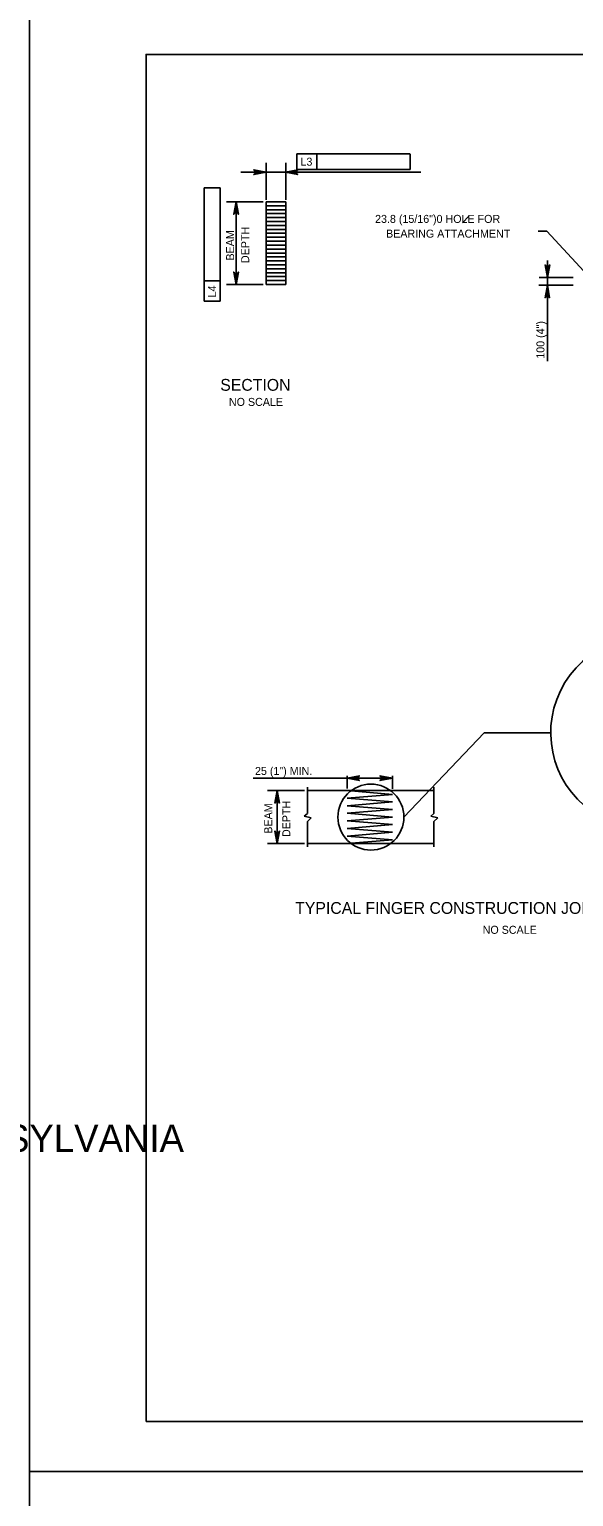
# Model space of a CAD drawing. Extents: x -13 to 81, y -176 to 0.
# Drawn here: x 34 to 42.16, y -66.38 to -44.38 of the extents above; entities that cross this region are included whole.
import ezdxf

# ---------------------------------------------------------------- set-up
doc = ezdxf.new("R2010")
doc.units = 0
for name, color, linetype in [('Level 1', 7, 'Continuous'), ('Level 2', 7, 'Continuous'), ('Level 5', 7, 'Continuous'), ('Level 6', 7, 'Continuous'), ('Level 63', 7, 'Continuous'), ('Level 7', 7, 'Continuous'), ('Level 8', 7, 'Continuous')]:
    doc.layers.add(name, color=color, linetype=linetype)

msp = doc.modelspace()

# ---------------------------------------------------------------- linework, layer by layer
at = {"layer": 'Level 1'}
msp.add_lwpolyline([(35.75, -65.25), (67.25, -65.25), (67.25, -44.75), (35.75, -44.75)], close=True, dxfattribs=at)
at = {"layer": 'Level 2'}
for p, q in [((37.553, -48.201), (37.553, -46.961)), ((37.553, -46.961), (37.848, -46.961)), ((37.848, -46.961), (37.848, -48.201)), ((37.848, -48.201), (37.553, -48.201))]:
    msp.add_line(p, q, dxfattribs=at)
at = {"layer": 'Level 5'}
for p, q in [((37.553, -46.931), (37.553, -46.378)), ((37.848, -46.931), (37.848, -46.378)), ((38.01, -46.241), (38.01, -46.477)), ((38.01, -46.241), (38.313, -46.241)), ((38.313, -46.241), (38.313, -46.477)), ((38.313, -46.241), (39.705, -46.241)), ((39.711, -46.241), (39.711, -46.477)), ((37.172, -46.518), (39.871, -46.518)), ((38.01, -46.477), (39.711, -46.477)), ((36.624, -46.75), (36.861, -46.75)), ((36.624, -48.148), (36.624, -46.75)), ((36.861, -48.451), (36.861, -46.75)), ((37.508, -46.961), (36.955, -46.961)), ((37.101, -48.201), (37.101, -46.961)), ((40.592, -47.178), (40.496, -47.274)), ((41.76, -47.399), (41.632, -47.399)), ((42.383, -48.07), (41.76, -47.399)), ((41.77, -49.352), (41.77, -47.842)), ((36.624, -48.451), (36.624, -48.148)), ((36.624, -48.148), (36.861, -48.148)), ((42.158, -48.095), (41.646, -48.095)), ((37.508, -48.201), (36.955, -48.201)), ((42.155, -48.213), (41.643, -48.213)), ((36.624, -48.451), (36.861, -48.451)), ((37.355, -55.603), (39.445, -55.603)), ((38.765, -55.758), (38.765, -55.565)), ((39.445, -55.764), (39.445, -55.568)), ((38.125, -55.789), (37.572, -55.789)), ((37.718, -56.583), (37.718, -55.789)), ((38.17, -56.131), (38.17, -55.739)), ((40.069, -55.739), (40.069, -56.133)), ((38.17, -56.131), (38.124, -56.17)), ((38.124, -56.17), (38.228, -56.197)), ((38.228, -56.197), (38.17, -56.251)), ((38.17, -56.634), (38.17, -56.251)), ((40.069, -56.133), (40.023, -56.172)), ((40.023, -56.172), (40.127, -56.199)), ((40.127, -56.199), (40.069, -56.253)), ((40.069, -56.253), (40.069, -56.634)), ((38.125, -56.583), (37.572, -56.583))]:
    msp.add_line(p, q, dxfattribs=at)
for points in [[(37.553, -46.518), (37.366, -46.553), (37.38, -46.543), (37.388, -46.53), (37.39, -46.518), (37.388, -46.505), (37.38, -46.493), (37.366, -46.483), (37.553, -46.518), (37.38, -46.493), (37.388, -46.505), (37.553, -46.518), (37.39, -46.518), (37.388, -46.53), (37.553, -46.518), (37.38, -46.543)], [(37.841, -46.518), (38.027, -46.483), (38.013, -46.493), (38.005, -46.505), (38.003, -46.518), (38.005, -46.53), (38.013, -46.543), (38.027, -46.553), (37.841, -46.518), (38.013, -46.543), (38.005, -46.53), (37.841, -46.518), (38.003, -46.518), (38.005, -46.505), (37.841, -46.518), (38.013, -46.493)], [(37.101, -46.961), (37.136, -47.147), (37.126, -47.133), (37.114, -47.125), (37.101, -47.123), (37.089, -47.125), (37.076, -47.133), (37.066, -47.147), (37.101, -46.961), (37.076, -47.133), (37.089, -47.125), (37.101, -46.961), (37.101, -47.123), (37.114, -47.125), (37.101, -46.961), (37.126, -47.133)], [(41.77, -48.095), (41.735, -47.908), (41.745, -47.922), (41.757, -47.93), (41.77, -47.932), (41.782, -47.93), (41.795, -47.922), (41.805, -47.908), (41.77, -48.095), (41.795, -47.922), (41.782, -47.93), (41.77, -48.095), (41.77, -47.932), (41.757, -47.93), (41.77, -48.095), (41.745, -47.922)], [(37.101, -48.201), (37.066, -48.015), (37.076, -48.029), (37.089, -48.036), (37.101, -48.038), (37.114, -48.036), (37.126, -48.029), (37.136, -48.015), (37.101, -48.201), (37.126, -48.029), (37.114, -48.036), (37.101, -48.201), (37.101, -48.038), (37.089, -48.036), (37.101, -48.201), (37.076, -48.029)], [(41.77, -48.213), (41.804, -48.399), (41.795, -48.385), (41.782, -48.377), (41.77, -48.375), (41.757, -48.377), (41.745, -48.385), (41.735, -48.399), (41.77, -48.213), (41.745, -48.385), (41.757, -48.377), (41.77, -48.213), (41.77, -48.375), (41.782, -48.377), (41.77, -48.213), (41.795, -48.385)], [(38.765, -55.603), (38.951, -55.569), (38.937, -55.578), (38.93, -55.591), (38.928, -55.603), (38.93, -55.616), (38.937, -55.628), (38.951, -55.638), (38.765, -55.603), (38.937, -55.628), (38.93, -55.616), (38.765, -55.603), (38.928, -55.603), (38.93, -55.591), (38.765, -55.603), (38.937, -55.578)], [(39.445, -55.603), (39.259, -55.638), (39.273, -55.628), (39.281, -55.616), (39.283, -55.603), (39.281, -55.591), (39.273, -55.578), (39.259, -55.569), (39.445, -55.603), (39.273, -55.578), (39.281, -55.591), (39.445, -55.603), (39.283, -55.603), (39.281, -55.616), (39.445, -55.603), (39.273, -55.628)], [(37.718, -55.789), (37.753, -55.976), (37.743, -55.961), (37.731, -55.954), (37.718, -55.952), (37.706, -55.954), (37.694, -55.961), (37.684, -55.976), (37.718, -55.789), (37.694, -55.961), (37.706, -55.954), (37.718, -55.789), (37.718, -55.952), (37.731, -55.954), (37.718, -55.789), (37.743, -55.961)], [(37.718, -56.583), (37.684, -56.397), (37.694, -56.411), (37.706, -56.418), (37.718, -56.42), (37.731, -56.418), (37.743, -56.411), (37.753, -56.397), (37.718, -56.583), (37.743, -56.411), (37.731, -56.418), (37.718, -56.583), (37.718, -56.42), (37.706, -56.418), (37.718, -56.583), (37.694, -56.411)]]:
    msp.add_lwpolyline(points, dxfattribs=at)
at = {"layer": 'Level 6'}
for p, q in [((37.848, -47.02), (37.553, -47.02)), ((37.848, -47.079), (37.553, -47.079)), ((37.848, -47.138), (37.553, -47.138)), ((37.848, -47.197), (37.553, -47.197)), ((37.848, -47.256), (37.553, -47.256)), ((37.848, -47.315), (37.553, -47.315)), ((37.848, -47.374), (37.553, -47.374)), ((37.848, -47.433), (37.553, -47.433)), ((37.848, -47.492), (37.553, -47.492)), ((37.848, -47.551), (37.553, -47.551)), ((37.848, -47.611), (37.553, -47.611)), ((37.848, -47.669), (37.553, -47.669)), ((37.848, -47.729), (37.553, -47.729)), ((37.848, -47.788), (37.553, -47.788)), ((37.848, -47.847), (37.553, -47.847)), ((37.848, -47.906), (37.553, -47.906)), ((37.848, -47.965), (37.553, -47.965)), ((37.848, -48.024), (37.553, -48.024)), ((37.848, -48.083), (37.553, -48.083)), ((37.848, -48.142), (37.553, -48.142))]:
    msp.add_line(p, q, dxfattribs=at)
at = {"layer": 'Level 63'}
for points in [[(34, -66), (68, -66), (68, -44), (34, -44)], [(34, -88), (68, -88), (68, -66), (34, -66)]]:
    msp.add_lwpolyline(points, close=True, dxfattribs=at)
at = {"layer": 'Level 7'}
for p, q in [((38.17, -55.789), (40.069, -55.789)), ((38.765, -55.789), (39.445, -55.846)), ((39.445, -55.846), (38.765, -55.903)), ((38.765, -55.903), (39.445, -55.959)), ((39.445, -55.959), (38.765, -56.016)), ((38.765, -56.016), (39.445, -56.073)), ((39.445, -56.073), (38.765, -56.129)), ((38.765, -56.129), (39.445, -56.186)), ((39.445, -56.186), (38.765, -56.243)), ((38.765, -56.243), (39.445, -56.299)), ((39.445, -56.299), (38.765, -56.356)), ((38.765, -56.356), (39.445, -56.413)), ((39.445, -56.413), (38.765, -56.47)), ((38.765, -56.47), (39.445, -56.526)), ((39.445, -56.526), (38.765, -56.583)), ((40.069, -56.583), (38.17, -56.583))]:
    msp.add_line(p, q, dxfattribs=at)
msp.add_arc((43.259, -54.922), 1.438, 335.5215, 321.436, dxfattribs=at)
at = {"layer": 'Level 8'}
for p, q in [((39.618, -56.186), (40.824, -54.922)), ((40.824, -54.922), (41.821, -54.922))]:
    msp.add_line(p, q, dxfattribs=at)
msp.add_circle((39.123, -56.186), 0.495, dxfattribs=at)

# ---------------------------------------------------------------- texts
at = {"layer": 'Level 1'}
msp.add_text('COMMONWEALTH OF PENNSYLVANIA', height=0.41048, dxfattribs=at).set_placement((26.194, -61.207))
at = {"layer": 'Level 5'}
for s, rotation, p in [('L3', 359.9382, (38.067, -46.419)), ('BEAM', 90, (37.072, -47.842)), ('DEPTH', 90, (37.298, -47.879)), ('L4', 89.9382, (36.802, -48.394)), ('100 (4")', 90, (41.726, -49.314)), ('BEAM', 90, (37.644, -56.435)), ('DEPTH', 90, (37.915, -56.485))]:
    msp.add_text(s, height=0.12, rotation=rotation, dxfattribs=at).set_placement(p)
for s, height, p in [('23.8 (15/16")0 HOLE FOR', 0.12, (39.186, -47.277)), ('BEARING ATTACHMENT', 0.12, (39.351, -47.498)), ('SECTION', 0.1772, (36.864, -49.794)), ('NO SCALE', 0.12, (36.994, -50.021)), ('25 (1") MIN.', 0.12, (37.385, -55.554)), ('NO SCALE', 0.12, (40.8, -57.936))]:
    msp.add_text(s, height=height, dxfattribs=at).set_placement(p)
at = {"layer": 'Level 8'}
msp.add_text('TYPICAL FINGER CONSTRUCTION JOINT DETAIL', height=0.17717, dxfattribs=at).set_placement((37.988, -57.637))

doc.saveas('drawing.dxf')
